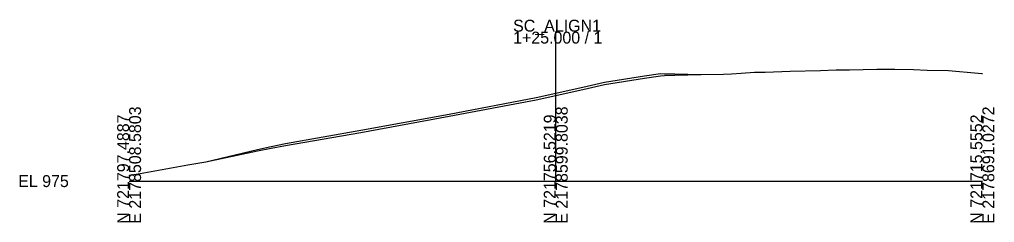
# Model space of a CAD drawing. Extents: x -2342 to 14913, y -10 to 5257.
# Drawn here: x -25.7 to 202.8, y 2490.3 to 2537.8 of the extents above; entities that cross this region are included whole.
import ezdxf

# ---------------------------------------------------------------- set-up
doc = ezdxf.new("R2010")
doc.units = 0
for name, color, linetype in [('Default', 7, 'Continuous'), ('GK_Cells', 7, 'Continuous'), ('SC_Scratch1', 7, 'Continuous'), ('XS_X_Ground_Line', 7, 'Continuous')]:
    doc.layers.add(name, color=color, linetype=linetype)

msp = doc.modelspace()

# ---------------------------------------------------------------- linework, layer by layer
at = {"layer": 'GK_Cells'}
for p, q in [((100, 2500), (100, 2535)), ((0, 2500), (100, 2500)), ((100, 2500), (200, 2500))]:
    msp.add_line(p, q, dxfattribs=at)
at = {"layer": 'SC_Scratch1'}
msp.add_lwpolyline([(0, 2501.34), (0.15, 2501.37), (2.58, 2501.8), (9.44, 2503), (13.73, 2503.78), (17.97, 2504.55), (30.12, 2507.07), (33.27, 2507.69), (36.62, 2508.33), (54.31, 2511.42), (75.02, 2515.18), (95.42, 2519.03), (106.37, 2521.47), (111.39, 2522.65), (120.84, 2524.11), (124.55, 2524.68), (125.52, 2524.7), (127.89, 2524.79), (134.09, 2524.96), (139.35, 2525.08), (141.18, 2525.1), (143.47, 2525.27), (146.59, 2525.52), (149.06, 2525.53), (154.95, 2525.72), (162.05, 2525.88), (165.74, 2526.02), (168.82, 2526.09), (175.25, 2526.22), (179.46, 2526.2), (183.83, 2526.14), (187.05, 2525.98), (192.05, 2525.92), (198.98, 2525.27), (199.84, 2525.17), (200, 2525.16)], dxfattribs=at)
at = {"layer": 'XS_X_Ground_Line'}
msp.add_lwpolyline([(0, 2501.34), (0.15, 2501.37), (2.58, 2501.8), (9.44, 2503), (13.73, 2503.78), (17.97, 2504.55), (30.12, 2507.43), (33.27, 2508.14), (36.62, 2508.84), (54.31, 2511.93), (75.02, 2515.69), (95.42, 2519.54), (106.37, 2521.98), (111.39, 2523.16), (120.84, 2524.62), (124.55, 2525.19), (125.52, 2525.14), (127.89, 2525.15), (134.09, 2524.96), (139.35, 2525.08), (141.18, 2525.1), (143.47, 2525.27), (146.59, 2525.52), (149.06, 2525.53), (154.95, 2525.72), (162.05, 2525.88), (165.74, 2526.02), (168.82, 2526.09), (175.25, 2526.22), (179.46, 2526.2), (183.83, 2526.14), (187.05, 2525.98), (192.05, 2525.92), (198.98, 2525.27), (199.84, 2525.17), (200, 2525.16)], dxfattribs=at)

# ---------------------------------------------------------------- texts
at = {"layer": 'Default'}
msp.add_text('-', height=0.0001, dxfattribs=at).set_placement((0, 2500))
at = {"layer": 'GK_Cells'}
for s, p in [('SC_ALIGN1', (90, 2535)), ('1+25.000 / 1', (90, 2532.2)), ('EL 975', (-26, 2498.6))]:
    msp.add_text(s, height=2.8, dxfattribs=at).set_placement(p)
for s, p in [('E 2178508.5803', (2.8, 2490)), ('E 2178599.8038', (102.8, 2490)), ('E 2178691.0272', (202.8, 2490)), ('N 721797.4887', (0, 2490)), ('N 721756.5219', (100, 2490)), ('N 721715.5552', (200, 2490))]:
    msp.add_text(s, height=2.8, rotation=90, dxfattribs=at).set_placement(p)
at = {"layer": 'SC_Scratch1'}
msp.add_text('X', height=0.0001, dxfattribs=at).set_placement((100, 2520.56))

doc.saveas('drawing.dxf')
